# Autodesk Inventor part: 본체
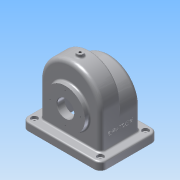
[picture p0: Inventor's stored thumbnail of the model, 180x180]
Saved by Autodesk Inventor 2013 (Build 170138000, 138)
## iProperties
Created: 2017-11
Part Number: 본체
Material: 알루미늄 6061
Document SubType Name: Modeling
Designer: Administrator
Density: 2.71 g/cm^3
Mass: 980.193 g
Surface Area: 1149.36 cm^2
Volume: 361.695 cm^3
Author: Administrator
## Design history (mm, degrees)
sketch "스케치1"
  geometry: L1 (-58, 80)-(-58, 0); L2 (58, 80)-(58, 0); L3 (-58, 0)-(58, 0); A1 r 58 centre (0, 80) between (58, 80) and (-58, 80); 2 further points
  constraints: 6 end point, 2 point on circle, 2 tangent, 1 centre point, 1 coincident, 1 parallel, 1 perpendicular, 1 vertical, 1 vertical alignment
  dimensions: "d0" = 116 diameter of A1; "d2" = 80 distance of point (0, 0) A1.centre; "d3" = 80 distance from line of L3 A1.centre
extrude "돌출1" new body sketch "스케치1" stored distance "d4" = 38; taper "d5" = 0 deg
sketch "스케치2"
  geometry: L1 (-58, 80)-(-58, 0) reference; L2 (-58, 0)-(58, 0) reference; L3 (58, 0)-(58, 80) reference; L4 (-58, 57)-(-58, 1.222); L5 (58, 57)-(58, 0); L6 (58, 0)-(-58, 0); A1 r 58 centre (0, 57) between (10.724, 0) and (-10.724, 0); 3 further points
  constraints: 6 end point, 6 point on line, 4 point on circle, 2 collinear, 1 centre point, 1 midpoint, 1 vertical alignment
  dimensions: "d6" = 116 diameter of A1; "d7" = 57 distance of point (0, 0) A1.centre
extrude "돌출2" join sketch "스케치2" distance "d8" = 38; taper "d9" = 0 deg
feature "쉘1" dims "d10" = 5
fillet "모깎기1" dims "d11" = 3
sketch "스케치6"
  geometry: L1 (116, 0)-(116, -76) reference; L2 (0, 0)-(116, 0) reference; L3 (0, 0)-(0, -76) reference; L4 (116, -76)-(0, -76) reference; L5 (-17, 17)-(133, 17); L6 (133, 17)-(133, -93); L7 (133, -93)-(-17, -93); L8 (-17, -93)-(-17, 17); L9 (-17, 17)-(133, -93); L10 (133, 17)-(-17, -93); 6 further points
  constraints: 12 end point, 6 midpoint, 2 parallel, 1 horizontal, 1 horizontal alignment, 1 perpendicular, 1 vertical alignment
  dimensions: "d20" = 150 distance of L6.end L7.end; "d21" = 110 distance of L5.end L6.end
extrude "돌출4" join sketch "스케치6" distance "d22" = 15; taper "d23" = 0 deg
fillet "모깎기4" dims "d24" = 8
fillet "모깎기5" dims "d25" = 3, "d26" = 12
sketch "스케치7"
  geometry: A1 r 12 centre (121, 81) between (133, 81) and (121, 93) reference; A2 r 12 centre (-5, 81) between (-5, 93) and (-17, 81) reference; A3 r 12 centre (-5, -5) between (-17, -5) and (-5, -17) reference; A4 r 12 centre (121, -5) between (121, -17) and (133, -5) reference; 5 further points
  constraints: 4 coincident
hole "구멍1" sketch "스케치7" at (-5, 81), (-5, -5), (121, -5), (121, 81) diameter "d27" = 5; stored, may be unused: countersink angle "d31" = 90 deg, drill point angle "d33" = 0 deg; dims "d28" = 6, "d29" = 12, "d30" = 5, "d32" = 8
fillet "모깎기6" dims "d34" = 3
sketch "스케치8"
  geometry: L1 (-63, 0)-(63, 0) reference; C1 r 37.5 at (0, 65); A1 r 50 centre (0, 80) between (50, 80) and (-50, 80) reference; 1 further point
  constraints: 1 centre point, 1 vertical alignment
  dimensions: "d35" = 75 diameter of C1; "d36" = 65 distance from line of L1 C1.centre
extrude "돌출5" join sketch "스케치8" distance "d37" = 9; taper "d38" = 0 deg
sketch "스케치9"
  geometry: C1 r 37.5 at (0, 0) reference; C2 r 16 at (0, 0); 1 further point
  constraints: 1 centre point, 1 coincident
  dimensions: "d39" = 32 diameter of C2
extrude "돌출6" cut sketch "스케치9" stored distance "d40" = 9; taper "d41" = 0 deg
sketch "스케치10"
  geometry: C1 r 16 at (0, 0) reference; 2 further points
  constraints: 1 vertical alignment
  dimensions: "d42" = 29 distance of C1.centre point (0, 29)
hole "구멍2" sketch "스케치10" at (0, 29) diameter "d43" = 2.459; stored, may be unused: countersink angle "d47" = 90 deg, drill point angle "d49" = 118 deg; dims "d44" = 6, "d45" = 12, "d46" = 5, "d48" = 8
fillet "모깎기7" dims "d53" = 3
sketch "스케치11"
  geometry: L1 (-63, 0)-(63, 0) reference; C1 r 31 at (0, 65); A1 r 50 centre (0, 57) between (50, 57) and (-50, 57) reference; 1 further point
  constraints: 1 centre point, 1 vertical alignment
  dimensions: "d54" = 62 diameter of C1; "d55" = 65 distance from line of L1 C1.centre
extrude "돌출7" join sketch "스케치11" distance "d56" = 10; taper "d57" = 0 deg
sketch "스케치12"
  geometry: C1 r 31 at (0, 0) reference; C2 r 16 at (0, 0); 1 further point
  constraints: 1 centre point, 1 coincident
  dimensions: "d58" = 32 diameter of C2
extrude "돌출8" cut sketch "스케치12" stored distance "d59" = 10; taper "d60" = 0 deg
sketch "스케치13"
  geometry: C1 r 16 at (0, 0) reference; 2 further points
  constraints: 1 vertical alignment
  dimensions: "d61" = 26 distance of C1.centre point (0, 26)
hole "구멍3" sketch "스케치13" at (0, 26) diameter "d62" = 2.459; stored, may be unused: countersink angle "d66" = 90 deg, drill point angle "d68" = 118 deg; dims "d63" = 6, "d64" = 12, "d65" = 5, "d67" = 8
node "작업 평면1"
sketch "스케치14"
  geometry: L1 (-25.5, -8)-(-100.5, -8) reference; C1 r 6 at (-63, -36); 1 further point
  constraints: 1 centre point, 1 coincident
  dimensions: "d73" = 12 diameter of C1; "d74" = 28 distance from line of C1.centre L1
extrude "돌출9" join sketch "스케치14" stored distance "d75" = 10; taper "d76" = 0 deg
hole "구멍4" diameter "d79" = 4.459; stored, may be unused: countersink angle "d83" = 90 deg, drill point angle "d85" = 118 deg; dims "d77" = 10, "d78" = 10, "d80" = 6, "d81" = 12, "d82" = 5, "d84" = 8
fillet "모깎기8" dims "d86" = 3
chamfer "모따기1" distance "d87" = 1; stored, may be unused: second distance "d88" = 2, angle "d89" = 45 deg
sketch "스케치15"
  geometry: L1 (-35, 23)-(-35, -39) reference; L2 (-40, -57)-(46, -57) reference; 2 further points
  constraints: 1 other
  dimensions: "d90" = 38 distance from line of L1 point (3, -17); "d91" = 40 distance from line of L2 point (3, -17)
feature "엠보싱1" sketch "스케치15" dims "d0" = 116, "d2" = 80, "d3" = 80, "d92" = 0.5, "d93" = 0
fillet "모깎기10" dims "d95" = 3
node "솔리드1"
pattern_circular "원형 패턴1" dims angle "d51" = 360 deg
pattern_circular "원형 패턴2" dims angle "d70" = 360 deg
other parameters: "d72" = -144
